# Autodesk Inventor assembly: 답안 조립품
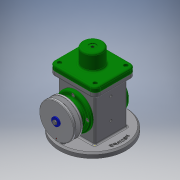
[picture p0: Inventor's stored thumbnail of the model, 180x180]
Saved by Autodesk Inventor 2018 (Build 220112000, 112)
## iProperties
Created: 2019-08
Part Number: 답안 조립품
Material: 일반
Document SubType Name: Assembly
Designer: USER
Author: USER
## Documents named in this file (18)
- C:\Users\USER\Desktop\490804V1017\답안 조립품.iam
- C:\Users\USER\Desktop\490804V1017\본체.ipt
- C:\Users\USER\Desktop\490804V1017\E-링.ipt
- C:\Users\USER\Desktop\490804V1017\V-벨트풀리.ipt
- C:\Users\USER\Desktop\490804V1017\덮개.ipt
- C:\Users\USER\Desktop\490804V1017\뒤커버.ipt
- C:\Users\USER\Desktop\490804V1017\링크.ipt
- C:\Users\USER\Desktop\490804V1017\베어링 17 x 40 x 12.ipt
- C:\Users\USER\Desktop\490804V1017\볼트 M4 x 8.ipt
- C:\Users\USER\Desktop\490804V1017\볼트 M4 x 10.ipt
- C:\Users\USER\Desktop\490804V1017\슬라이더.ipt
- C:\Users\USER\Desktop\490804V1017\앞커버.ipt
- C:\Users\USER\Desktop\490804V1017\오일 실 17 30 8.ipt
- C:\Users\USER\Desktop\490804V1017\와셔 4x16.ipt
- C:\Users\USER\Desktop\490804V1017\클레비스 핀 6 x 22.ipt
- 클레비스 핀 6 x 22.ipt
- C:\Users\USER\Desktop\490804V1017\키 4 x 4 x 12.ipt
- C:\Users\USER\Desktop\490804V1017\편심축.ipt
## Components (2 placed, 2 different names)
1. E-링:1
2. V-벨트풀리:1
